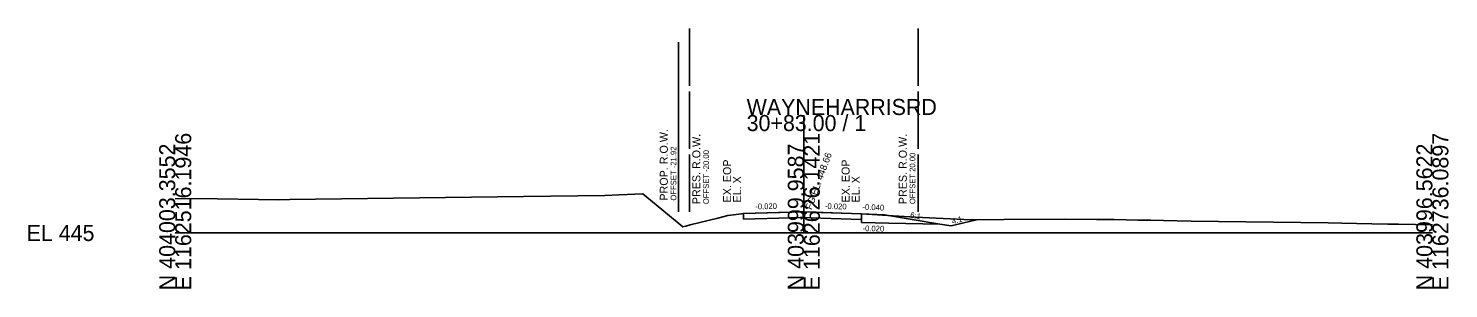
# Model space of a CAD drawing. Extents: x -26 to 223, y -10 to 1557.
# Drawn here: x -25.7 to 222.8, y 990.3 to 1035.7 of the extents above; entities that cross this region are included whole.
import ezdxf

# ---------------------------------------------------------------- set-up
doc = ezdxf.new("R2010")
doc.units = 0
for name, color, linetype in [('DESIGN - ROW - Right-of-Way Linework', 7, 'Continuous'), ('DESIGN - SCRATCH - User 2', 7, 'Continuous'), ('DESIGN - SHEET - Light Grid', 7, 'Continuous'), ('DESIGN - TYPICAL - Finished Grade and Subgrade', 7, 'Continuous'), ('DESIGN - TYPICAL - Finished Grade Slopes Text', 7, 'Continuous'), ('DESIGN - TYPICAL - Subgrade Cross Slope Text', 7, 'Continuous'), ('DESIGN - TYPICAL - Text', 7, 'Continuous'), ('SURVEY - GROUND - Top of Ground', 7, 'Continuous'), ('SURVEY - PROPERTY - ROW Lines', 7, 'Continuous'), ('SURVEY - PROPERTY - ROW Lines Text', 7, 'Continuous')]:
    doc.layers.add(name, color=color, linetype=linetype)

msp = doc.modelspace()

# ---------------------------------------------------------------- linework, layer by layer
at = {"layer": 'DESIGN - SHEET - Light Grid'}
for p, q in [((110, 1000), (110, 1020.59)), ((0, 1000), (110, 1000)), ((110, 1000), (220, 1000))]:
    msp.add_line(p, q, dxfattribs=at)
at = {"layer": 'DESIGN - TYPICAL - Finished Grade and Subgrade'}
for p, q in [((88.08, 1003.69), (88.08, 1033.29)), ((110, 1003.69), (99.46, 1003.4)), ((99.46, 1003.4), (99.46, 1002.4)), ((110, 1003.69), (120.11, 1003.33)), ((120.11, 1003.33), (124.11, 1003.17)), ((120.11, 1003.33), (120.11, 1002.33)), ((120.11, 1003.33), (120.11, 1001.83)), ((120.11, 1001.83), (124.89, 1001.73)), ((124.11, 1003.17), (133.79, 1001.56)), ((133.79, 1001.56), (124.89, 1001.73)), ((140.2, 1002.32), (135.79, 1001.22)), ((133.79, 1001.56), (135.79, 1001.22))]:
    msp.add_line(p, q, dxfattribs=at)
msp.add_lwpolyline([(99.46, 1002.4), (107.66, 1002.66), (109.36, 1002.72), (109.96, 1002.69), (111.19, 1002.65), (120.11, 1002.33)], dxfattribs=at)
at = {"layer": 'SURVEY - GROUND - Top of Ground'}
msp.add_lwpolyline([(0, 1005.94), (3.83, 1006.03), (18.12, 1005.79), (20.04, 1005.83), (24.54, 1005.93), (60.97, 1006.35), (75.19, 1006.54), (77.68, 1006.64), (81.85, 1006.86), (82.21, 1006.55), (88.86, 1001.08), (89.35, 1001.2), (90.09, 1001.43), (94.96, 1002.6), (96.68, 1003.03), (97.24, 1003.11), (99.11, 1003.37), (99.46, 1003.4), (107.63, 1003.66), (109.36, 1003.72), (110, 1003.69), (111.22, 1003.65), (120.11, 1003.33), (125.64, 1002.99), (129.56, 1002.77), (135.62, 1002.48), (139.23, 1002.32), (145.03, 1002.36), (155.64, 1002.39), (161.2, 1002.37), (164.3, 1002.34), (166.4, 1002.3), (168.46, 1002.26), (170.75, 1002.22), (172.97, 1002.18), (175.32, 1002.13), (177.81, 1002.09), (201.76, 1001.75), (204.17, 1001.7), (206.71, 1001.65), (209.38, 1001.6), (212.21, 1001.54), (214.06, 1001.51), (217.07, 1001.47), (220, 1001.42)], dxfattribs=at)
at = {"layer": 'SURVEY - PROPERTY - ROW Lines'}
for p, q in [((90, 1025.69), (90, 1035.69)), ((130, 1025.69), (130, 1035.69)), ((90, 1014.69), (90, 1024.69)), ((130, 1014.69), (130, 1024.69)), ((90, 1003.69), (90, 1013.69)), ((130, 1003.69), (130, 1013.69))]:
    msp.add_line(p, q, dxfattribs=at)

# ---------------------------------------------------------------- texts
at = {"layer": 'DESIGN - ROW - Right-of-Way Linework'}
for s, height, p in [('PROP. R.O.W.', 1.4, (86.2, 1005.65)), ('OFFSET -21.92', 1, (87.7, 1005.65))]:
    msp.add_text(s, height=height, rotation=90, dxfattribs=at).set_placement(p)
at = {"layer": 'DESIGN - SCRATCH - User 2'}
for s, p in [('EX. EOP', (97.28, 1005.33)), ('EX. EOP', (118.02, 1005.33)), ('EL. X', (99.03, 1005.33)), ('EL. X', (119.77, 1005.33))]:
    msp.add_text(s, height=1.4, rotation=90, dxfattribs=at).set_placement(p)
at = {"layer": 'DESIGN - SHEET - Light Grid'}
for s, p in [('WAYNEHARRISRD', (100, 1020.59)), ('30+83.00 / 1', (100, 1017.79)), ('EL 445', (-26, 998.6))]:
    msp.add_text(s, height=2.8, dxfattribs=at).set_placement(p)
for s, p in [('E 1162516.1946', (2.8, 990)), ('E 1162626.1421', (112.8, 990)), ('E 1162736.0897', (222.8, 990)), ('N 404003.3552', (0, 990)), ('N 403999.9587', (110, 990)), ('N 403996.5622', (220, 990))]:
    msp.add_text(s, height=2.8, rotation=90, dxfattribs=at).set_placement(p)
at = {"layer": 'DESIGN - TYPICAL - Finished Grade Slopes Text'}
for s, rotation, p in [('-0.020', 1.1458, (101.52, 1004.12)), ('-0.020', 358.8542, (113.69, 1004.19)), ('-0.040', 357.7094, (120.25, 1004.07)), ('6:1', 350.5377, (128.56, 1002.67)), ('4:1', 14.4363, (136.04, 1001.53))]:
    msp.add_text(s, height=1, rotation=rotation, dxfattribs=at).set_placement(p)
at = {"layer": 'DESIGN - TYPICAL - Subgrade Cross Slope Text'}
msp.add_text('-0.020', height=1, rotation=358.8542, dxfattribs=at).set_placement((120.27, 1000.32))
at = {"layer": 'DESIGN - TYPICAL - Text'}
msp.add_text('  FG EL. 448.66', height=1.2, rotation=70, dxfattribs=at).set_placement((111.06, 1003.13))
at = {"layer": 'SURVEY - PROPERTY - ROW Lines Text'}
for s, height, p in [('PRES. R.O.W.', 1.4, (91.9, 1005.03)), ('PRES. R.O.W.', 1.4, (128.02, 1005.03)), ('OFFSET -20.00', 1, (93.4, 1005.03)), ('OFFSET 20.00', 1, (129.52, 1005.03))]:
    msp.add_text(s, height=height, rotation=90, dxfattribs=at).set_placement(p)

doc.saveas('drawing.dxf')
